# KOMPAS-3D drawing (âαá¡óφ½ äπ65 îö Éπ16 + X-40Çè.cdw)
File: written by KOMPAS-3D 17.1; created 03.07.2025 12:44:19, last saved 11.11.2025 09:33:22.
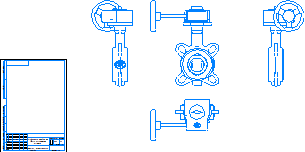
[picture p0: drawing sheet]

Sheet 1: A4, portrait

Title block, sheet 1: name: Гранвэл Ду65 МФ Ру16 + / X-40АК (Габаритный / чертёж); material: Сталь 20  ГОСТ 1050-2013; mass: 3,57; sheets: 1; sheet format: A4; stored path: \\adlc.lan\data\АДЛ_ПКД\3D-модели\ADL production\Дисковые поворотные затворы ГРАНВЭЛ\межфланцевый с китайским редуктором Ру16\KOMPAS 2D\Гранвэл Ду65 МФ Ру16 + X-40АК.cdw

Views: Вид 1, Спереди, Проекционный вид 2, Проекционный вид 3, Проекционный вид 4
Referenced files in \\adlc.lan\data\АДЛ_ПКД\3D-модели\ADL production\Дисковые поворотные затворы ГРАНВЭЛ\межфланцевый с китайским редуктором Ру16\KOMPAS 3D\: Гранвэл Ду65 МФ Ру16 + X-40АК.m3d
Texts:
  Andrey
  АДЛ
Dimensions and other numbers on the sheet: 1:1; 1; 3,57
